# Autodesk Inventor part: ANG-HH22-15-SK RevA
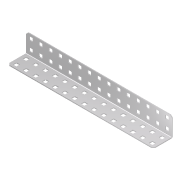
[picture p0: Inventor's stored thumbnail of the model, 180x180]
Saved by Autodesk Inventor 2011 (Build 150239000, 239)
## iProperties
Created: 2007-12
Part Number: ANG-HH22-15-SK RevA
Document SubType Name: Modeling
Density: 1 g/cm^3
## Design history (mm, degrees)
feature "Base1"
workplane "Work Plane1"
workplane "Work Plane2"
sketch "Sketch1" dims "d5" = 25.4
  geometry: L1 (2.286, -23.419)-(188.214, -23.419) reference; L2 (188.214, -23.419)-(190.5, -21.133) reference; L3 (190.5, -21.133)-(190.5, 0) reference; L4 (0, 0)-(190.5, 0) reference; L5 (0, 0)-(0, -21.133) reference; L6 (0, -21.133)-(2.286, -23.419) reference; L7 (186.461, -3.734)-(186.461, -7.341) reference; L8 (185.953, -7.849)-(182.347, -7.849) reference; L9 (181.839, -7.341)-(181.839, -3.734) reference; L10 (182.347, -3.226)-(185.953, -3.226) reference; L11 (173.761, -16.434)-(173.761, -20.041) reference; L12 (173.253, -20.549)-(169.647, -20.549) reference; L13 (169.139, -20.041)-(169.139, -16.434) reference; L14 (169.647, -15.926)-(173.253, -15.926) reference; L15 (173.761, -3.734)-(173.761, -7.341) reference; L16 (173.253, -7.849)-(169.647, -7.849) reference; L17 (169.139, -7.341)-(169.139, -3.734) reference; L18 (169.647, -3.226)-(173.253, -3.226) reference; L19 (161.061, -16.434)-(161.061, -20.041) reference; L20 (160.553, -20.549)-(156.947, -20.549) reference; L21 (156.439, -20.041)-(156.439, -16.434) reference; L22 (156.947, -15.926)-(160.553, -15.926) reference; L23 (161.061, -3.734)-(161.061, -7.341) reference; L24 (160.553, -7.849)-(156.947, -7.849) reference; L25 (156.439, -7.341)-(156.439, -3.734) reference; L26 (156.947, -3.226)-(160.553, -3.226) reference; L27 (148.361, -16.434)-(148.361, -20.041) reference; L28 (147.853, -20.549)-(144.247, -20.549) reference; L29 (143.739, -20.041)-(143.739, -16.434) reference; L30 (144.247, -15.926)-(147.853, -15.926) reference; L31 (148.361, -3.734)-(148.361, -7.341) reference; L32 (147.853, -7.849)-(144.247, -7.849) reference; L33 (143.739, -7.341)-(143.739, -3.734) reference; L34 (144.247, -3.226)-(147.853, -3.226) reference; L35 (135.661, -16.434)-(135.661, -20.041) reference; L36 (135.153, -20.549)-(131.547, -20.549) reference; L37 (131.039, -20.041)-(131.039, -16.434) reference; L38 (131.547, -15.926)-(135.153, -15.926) reference; L39 (135.661, -3.734)-(135.661, -7.341) reference; L40 (135.153, -7.849)-(131.547, -7.849) reference; L41 (131.039, -7.341)-(131.039, -3.734) reference; L42 (131.547, -3.226)-(135.153, -3.226) reference; L43 (122.961, -16.434)-(122.961, -20.041) reference; L44 (122.453, -20.549)-(118.847, -20.549) reference; L45 (118.339, -20.041)-(118.339, -16.434) reference; L46 (118.847, -15.926)-(122.453, -15.926) reference; L47 (122.961, -3.734)-(122.961, -7.341) reference; L48 (122.453, -7.849)-(118.847, -7.849) reference; L49 (118.339, -7.341)-(118.339, -3.734) reference; L50 (118.847, -3.226)-(122.453, -3.226) reference; L51 (110.261, -16.434)-(110.261, -20.041) reference; L52 (109.753, -20.549)-(106.147, -20.549) reference; L53 (105.639, -20.041)-(105.639, -16.434) reference; L54 (106.147, -15.926)-(109.753, -15.926) reference; L55 (110.261, -3.734)-(110.261, -7.341) reference; L56 (109.753, -7.849)-(106.147, -7.849) reference; L57 (105.639, -7.341)-(105.639, -3.734) reference; L58 (106.147, -3.226)-(109.753, -3.226) reference; L59 (97.561, -16.434)-(97.561, -20.041) reference; L60 (97.053, -20.549)-(93.447, -20.549) reference; L61 (92.939, -20.041)-(92.939, -16.434) reference; L62 (93.447, -15.926)-(97.053, -15.926) reference; L63 (97.561, -3.734)-(97.561, -7.341) reference; L64 (97.053, -7.849)-(93.447, -7.849) reference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; C1 r 2.311 at (184.15, -18.237); C2 r 2.311 at (171.45, -18.237); C3 r 2.311 at (158.75, -18.237); C4 r 2.311 at (146.05, -18.237); C5 r 2.311 at (133.35, -18.237); C6 r 2.311 at (120.65, -18.237); C7 r 2.311 at (107.95, -18.237); C8 r 2.311 at (95.25, -18.237); C9 r 2.311 at (82.55, -18.237); C10 r 2.311 at (69.85, -18.237); C11 r 2.311 at (57.15, -18.237); C12 r 2.311 at (44.45, -18.237); C13 r 2.311 at (31.75, -18.237); C14 r 2.311 at (19.05, -18.237); C15 r 2.311 at (6.35, -18.237); A1 r 0.508 centre (185.953, -7.341) between (185.953, -7.849) and (186.461, -7.341) reference; A2 r 0.508 centre (182.347, -7.341) between (181.839, -7.341) and (182.347, -7.849) reference; A3 r 0.508 centre (182.347, -3.734) between (182.347, -3.226) and (181.839, -3.734) reference; A4 r 0.508 centre (185.953, -3.734) between (186.461, -3.734) and (185.953, -3.226) reference; A5 r 0.508 centre (173.253, -20.041) between (173.253, -20.549) and (173.761, -20.041) reference; A6 r 0.508 centre (169.647, -20.041) between (169.139, -20.041) and (169.647, -20.549) reference; A7 r 0.508 centre (169.647, -16.434) between (169.647, -15.926) and (169.139, -16.434) reference; A8 r 0.508 centre (173.253, -16.434) between (173.761, -16.434) and (173.253, -15.926) reference; A9 r 0.508 centre (173.253, -7.341) between (173.253, -7.849) and (173.761, -7.341) reference; A10 r 0.508 centre (169.647, -7.341) between (169.139, -7.341) and (169.647, -7.849) reference; A11 r 0.508 centre (169.647, -3.734) between (169.647, -3.226) and (169.139, -3.734) reference; A12 r 0.508 centre (173.253, -3.734) between (173.761, -3.734) and (173.253, -3.226) reference; A13 r 0.508 centre (160.553, -20.041) between (160.553, -20.549) and (161.061, -20.041) reference; A14 r 0.508 centre (156.947, -20.041) between (156.439, -20.041) and (156.947, -20.549) reference; A15 r 0.508 centre (156.947, -16.434) between (156.947, -15.926) and (156.439, -16.434) reference; A16 r 0.508 centre (160.553, -16.434) between (161.061, -16.434) and (160.553, -15.926) reference; A17 r 0.508 centre (160.553, -7.341) between (160.553, -7.849) and (161.061, -7.341) reference; A18 r 0.508 centre (156.947, -7.341) between (156.439, -7.341) and (156.947, -7.849) reference; A19 r 0.508 centre (156.947, -3.734) between (156.947, -3.226) and (156.439, -3.734) reference; A20 r 0.508 centre (160.553, -3.734) between (161.061, -3.734) and (160.553, -3.226) reference; A21 r 0.508 centre (147.853, -20.041) between (147.853, -20.549) and (148.361, -20.041) reference; A22 r 0.508 centre (144.247, -20.041) between (143.739, -20.041) and (144.247, -20.549) reference; A23 r 0.508 centre (144.247, -16.434) between (144.247, -15.926) and (143.739, -16.434) reference; A24 r 0.508 centre (147.853, -16.434) between (148.361, -16.434) and (147.853, -15.926) reference; A25 r 0.508 centre (147.853, -7.341) between (147.853, -7.849) and (148.361, -7.341) reference; A26 r 0.508 centre (144.247, -7.341) between (143.739, -7.341) and (144.247, -7.849) reference; A27 r 0.508 centre (144.247, -3.734) between (144.247, -3.226) and (143.739, -3.734) reference; A28 r 0.508 centre (147.853, -3.734) between (148.361, -3.734) and (147.853, -3.226) reference; A29 r 0.508 centre (135.153, -20.041) between (135.153, -20.549) and (135.661, -20.041) reference; A30 r 0.508 centre (131.547, -20.041) between (131.039, -20.041) and (131.547, -20.549) reference; A31 r 0.508 centre (131.547, -16.434) between (131.547, -15.926) and (131.039, -16.434) reference; A32 r 0.508 centre (135.153, -16.434) between (135.661, -16.434) and (135.153, -15.926) reference; A33 r 0.508 centre (135.153, -7.341) between (135.153, -7.849) and (135.661, -7.341) reference; A34 r 0.508 centre (131.547, -7.341) between (131.039, -7.341) and (131.547, -7.849) reference; A35 r 0.508 centre (131.547, -3.734) between (131.547, -3.226) and (131.039, -3.734) reference; A36 r 0.508 centre (135.153, -3.734) between (135.661, -3.734) and (135.153, -3.226) reference; A37 r 0.508 centre (122.453, -20.041) between (122.453, -20.549) and (122.961, -20.041) reference; A38 r 0.508 centre (118.847, -20.041) between (118.339, -20.041) and (118.847, -20.549) reference; A39 r 0.508 centre (118.847, -16.434) between (118.847, -15.926) and (118.339, -16.434) reference; A40 r 0.508 centre (122.453, -16.434) between (122.961, -16.434) and (122.453, -15.926) reference; A41 r 0.508 centre (122.453, -7.341) between (122.453, -7.849) and (122.961, -7.341) reference; A42 r 0.508 centre (118.847, -7.341) between (118.339, -7.341) and (118.847, -7.849) reference; A43 r 0.508 centre (118.847, -3.734) between (118.847, -3.226) and (118.339, -3.734) reference; A44 r 0.508 centre (122.453, -3.734) between (122.961, -3.734) and (122.453, -3.226) reference; A45 r 0.508 centre (109.753, -20.041) between (109.753, -20.549) and (110.261, -20.041) reference; A46 r 0.508 centre (106.147, -20.041) between (105.639, -20.041) and (106.147, -20.549) reference; A47 r 0.508 centre (106.147, -16.434) between (106.147, -15.926) and (105.639, -16.434) reference; A48 r 0.508 centre (109.753, -16.434) between (110.261, -16.434) and (109.753, -15.926) reference; A49 r 0.508 centre (109.753, -7.341) between (109.753, -7.849) and (110.261, -7.341) reference; A50 r 0.508 centre (106.147, -7.341) between (105.639, -7.341) and (106.147, -7.849) reference; A51 r 0.508 centre (106.147, -3.734) between (106.147, -3.226) and (105.639, -3.734) reference; A52 r 0.508 centre (109.753, -3.734) between (110.261, -3.734) and (109.753, -3.226) reference; A53 r 0.508 centre (97.053, -20.041) between (97.053, -20.549) and (97.561, -20.041) reference; A54 r 0.508 centre (93.447, -20.041) between (92.939, -20.041) and (93.447, -20.549) reference; A55 r 0.508 centre (93.447, -16.434) between (93.447, -15.926) and (92.939, -16.434) reference; A56 r 0.508 centre (97.053, -16.434) between (97.561, -16.434) and (97.053, -15.926) reference; A57 r 0.508 centre (97.053, -7.341) between (97.053, -7.849) and (97.561, -7.341) reference; A58 r 0.508 centre (93.447, -7.341) between (92.939, -7.341) and (93.447, -7.849) reference; A59 r 0.508 centre (93.447, -3.734) between (93.447, -3.226) and (92.939, -3.734) reference; A60 r 0.508 centre (97.053, -3.734) between (97.561, -3.734) and (97.053, -3.226) reference; A61 r 0.508 centre (84.353, -20.041) between (84.353, -20.549) and (84.861, -20.041) reference; A62 r 0.508 centre (80.747, -20.041) between (80.239, -20.041) and (80.747, -20.549) reference; A63 r 0.508 centre (80.747, -16.434) between (80.747, -15.926) and (80.239, -16.434) reference; A64 r 0.508 centre (84.353, -16.434) between (84.861, -16.434) and (84.353, -15.926) reference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
  constraints: 15 centre point, 3 tangent, 1 horizontal, 28 other
  dimensions: "d2" = 12.7 distance of C1.centre C2.centre
sketch "Sketch2" dims "d12" = 25.4
  geometry: L1 (190.5, 21.133)-(190.5, 0) reference; L2 (190.5, 21.133)-(188.214, 23.419) reference; L3 (2.286, 23.419)-(188.214, 23.419) reference; L4 (2.286, 23.419)-(0, 21.133) reference; L5 (0, 0)-(0, 21.133) reference; L6 (190.5, 0)-(0, 0) reference; L7 (186.461, 7.341)-(186.461, 3.734) reference; L8 (185.953, 3.226)-(182.347, 3.226) reference; L9 (181.839, 3.734)-(181.839, 7.341) reference; L10 (182.347, 7.849)-(185.953, 7.849) reference; L11 (173.761, 20.041)-(173.761, 16.434) reference; L12 (173.253, 15.926)-(169.647, 15.926) reference; L13 (169.139, 16.434)-(169.139, 20.041) reference; L14 (169.647, 20.549)-(173.253, 20.549) reference; L15 (173.761, 7.341)-(173.761, 3.734) reference; L16 (173.253, 3.226)-(169.647, 3.226) reference; L17 (169.139, 3.734)-(169.139, 7.341) reference; L18 (169.647, 7.849)-(173.253, 7.849) reference; L19 (161.061, 20.041)-(161.061, 16.434) reference; L20 (160.553, 15.926)-(156.947, 15.926) reference; L21 (156.439, 16.434)-(156.439, 20.041) reference; L22 (156.947, 20.549)-(160.553, 20.549) reference; L23 (161.061, 7.341)-(161.061, 3.734) reference; L24 (160.553, 3.226)-(156.947, 3.226) reference; L25 (156.439, 3.734)-(156.439, 7.341) reference; L26 (156.947, 7.849)-(160.553, 7.849) reference; L27 (148.361, 20.041)-(148.361, 16.434) reference; L28 (147.853, 15.926)-(144.247, 15.926) reference; L29 (143.739, 16.434)-(143.739, 20.041) reference; L30 (144.247, 20.549)-(147.853, 20.549) reference; L31 (148.361, 7.341)-(148.361, 3.734) reference; L32 (147.853, 3.226)-(144.247, 3.226) reference; L33 (143.739, 3.734)-(143.739, 7.341) reference; L34 (144.247, 7.849)-(147.853, 7.849) reference; L35 (135.661, 20.041)-(135.661, 16.434) reference; L36 (135.153, 15.926)-(131.547, 15.926) reference; L37 (131.039, 16.434)-(131.039, 20.041) reference; L38 (131.547, 20.549)-(135.153, 20.549) reference; L39 (135.661, 7.341)-(135.661, 3.734) reference; L40 (135.153, 3.226)-(131.547, 3.226) reference; L41 (131.039, 3.734)-(131.039, 7.341) reference; L42 (131.547, 7.849)-(135.153, 7.849) reference; L43 (122.961, 20.041)-(122.961, 16.434) reference; L44 (122.453, 15.926)-(118.847, 15.926) reference; L45 (118.339, 16.434)-(118.339, 20.041) reference; L46 (118.847, 20.549)-(122.453, 20.549) reference; L47 (122.961, 7.341)-(122.961, 3.734) reference; L48 (122.453, 3.226)-(118.847, 3.226) reference; L49 (118.339, 3.734)-(118.339, 7.341) reference; L50 (118.847, 7.849)-(122.453, 7.849) reference; L51 (110.261, 20.041)-(110.261, 16.434) reference; L52 (109.753, 15.926)-(106.147, 15.926) reference; L53 (105.639, 16.434)-(105.639, 20.041) reference; L54 (106.147, 20.549)-(109.753, 20.549) reference; L55 (110.261, 7.341)-(110.261, 3.734) reference; L56 (109.753, 3.226)-(106.147, 3.226) reference; L57 (105.639, 3.734)-(105.639, 7.341) reference; L58 (106.147, 7.849)-(109.753, 7.849) reference; L59 (97.561, 20.041)-(97.561, 16.434) reference; L60 (97.053, 15.926)-(93.447, 15.926) reference; L61 (92.939, 16.434)-(92.939, 20.041) reference; L62 (93.447, 20.549)-(97.053, 20.549) reference; L63 (97.561, 7.341)-(97.561, 3.734) reference; L64 (97.053, 3.226)-(93.447, 3.226) reference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; C1 r 2.311 at (184.15, 18.237); C2 r 2.311 at (171.45, 18.237); C3 r 2.311 at (158.75, 18.237); C4 r 2.311 at (146.05, 18.237); C5 r 2.311 at (133.35, 18.237); C6 r 2.311 at (120.65, 18.237); C7 r 2.311 at (107.95, 18.237); C8 r 2.311 at (95.25, 18.237); C9 r 2.311 at (82.55, 18.237); C10 r 2.311 at (69.85, 18.237); C11 r 2.311 at (57.15, 18.237); C12 r 2.311 at (44.45, 18.237); C13 r 2.311 at (31.75, 18.237); C14 r 2.311 at (19.05, 18.237); C15 r 2.311 at (6.35, 18.237); A1 r 0.508 centre (185.953, 3.734) between (185.953, 3.226) and (186.461, 3.734) reference; A2 r 0.508 centre (182.347, 3.734) between (181.839, 3.734) and (182.347, 3.226) reference; A3 r 0.508 centre (182.347, 7.341) between (182.347, 7.849) and (181.839, 7.341) reference; A4 r 0.508 centre (185.953, 7.341) between (186.461, 7.341) and (185.953, 7.849) reference; A5 r 0.508 centre (173.253, 16.434) between (173.253, 15.926) and (173.761, 16.434) reference; A6 r 0.508 centre (169.647, 16.434) between (169.139, 16.434) and (169.647, 15.926) reference; A7 r 0.508 centre (169.647, 20.041) between (169.647, 20.549) and (169.139, 20.041) reference; A8 r 0.508 centre (173.253, 20.041) between (173.761, 20.041) and (173.253, 20.549) reference; A9 r 0.508 centre (173.253, 3.734) between (173.253, 3.226) and (173.761, 3.734) reference; A10 r 0.508 centre (169.647, 3.734) between (169.139, 3.734) and (169.647, 3.226) reference; A11 r 0.508 centre (169.647, 7.341) between (169.647, 7.849) and (169.139, 7.341) reference; A12 r 0.508 centre (173.253, 7.341) between (173.761, 7.341) and (173.253, 7.849) reference; A13 r 0.508 centre (160.553, 16.434) between (160.553, 15.926) and (161.061, 16.434) reference; A14 r 0.508 centre (156.947, 16.434) between (156.439, 16.434) and (156.947, 15.926) reference; A15 r 0.508 centre (156.947, 20.041) between (156.947, 20.549) and (156.439, 20.041) reference; A16 r 0.508 centre (160.553, 20.041) between (161.061, 20.041) and (160.553, 20.549) reference; A17 r 0.508 centre (160.553, 3.734) between (160.553, 3.226) and (161.061, 3.734) reference; A18 r 0.508 centre (156.947, 3.734) between (156.439, 3.734) and (156.947, 3.226) reference; A19 r 0.508 centre (156.947, 7.341) between (156.947, 7.849) and (156.439, 7.341) reference; A20 r 0.508 centre (160.553, 7.341) between (161.061, 7.341) and (160.553, 7.849) reference; A21 r 0.508 centre (147.853, 16.434) between (147.853, 15.926) and (148.361, 16.434) reference; A22 r 0.508 centre (144.247, 16.434) between (143.739, 16.434) and (144.247, 15.926) reference; A23 r 0.508 centre (144.247, 20.041) between (144.247, 20.549) and (143.739, 20.041) reference; A24 r 0.508 centre (147.853, 20.041) between (148.361, 20.041) and (147.853, 20.549) reference; A25 r 0.508 centre (147.853, 3.734) between (147.853, 3.226) and (148.361, 3.734) reference; A26 r 0.508 centre (144.247, 3.734) between (143.739, 3.734) and (144.247, 3.226) reference; A27 r 0.508 centre (144.247, 7.341) between (144.247, 7.849) and (143.739, 7.341) reference; A28 r 0.508 centre (147.853, 7.341) between (148.361, 7.341) and (147.853, 7.849) reference; A29 r 0.508 centre (135.153, 16.434) between (135.153, 15.926) and (135.661, 16.434) reference; A30 r 0.508 centre (131.547, 16.434) between (131.039, 16.434) and (131.547, 15.926) reference; A31 r 0.508 centre (131.547, 20.041) between (131.547, 20.549) and (131.039, 20.041) reference; A32 r 0.508 centre (135.153, 20.041) between (135.661, 20.041) and (135.153, 20.549) reference; A33 r 0.508 centre (135.153, 3.734) between (135.153, 3.226) and (135.661, 3.734) reference; A34 r 0.508 centre (131.547, 3.734) between (131.039, 3.734) and (131.547, 3.226) reference; A35 r 0.508 centre (131.547, 7.341) between (131.547, 7.849) and (131.039, 7.341) reference; A36 r 0.508 centre (135.153, 7.341) between (135.661, 7.341) and (135.153, 7.849) reference; A37 r 0.508 centre (122.453, 16.434) between (122.453, 15.926) and (122.961, 16.434) reference; A38 r 0.508 centre (118.847, 16.434) between (118.339, 16.434) and (118.847, 15.926) reference; A39 r 0.508 centre (118.847, 20.041) between (118.847, 20.549) and (118.339, 20.041) reference; A40 r 0.508 centre (122.453, 20.041) between (122.961, 20.041) and (122.453, 20.549) reference; A41 r 0.508 centre (122.453, 3.734) between (122.453, 3.226) and (122.961, 3.734) reference; A42 r 0.508 centre (118.847, 3.734) between (118.339, 3.734) and (118.847, 3.226) reference; A43 r 0.508 centre (118.847, 7.341) between (118.847, 7.849) and (118.339, 7.341) reference; A44 r 0.508 centre (122.453, 7.341) between (122.961, 7.341) and (122.453, 7.849) reference; A45 r 0.508 centre (109.753, 16.434) between (109.753, 15.926) and (110.261, 16.434) reference; A46 r 0.508 centre (106.147, 16.434) between (105.639, 16.434) and (106.147, 15.926) reference; A47 r 0.508 centre (106.147, 20.041) between (106.147, 20.549) and (105.639, 20.041) reference; A48 r 0.508 centre (109.753, 20.041) between (110.261, 20.041) and (109.753, 20.549) reference; A49 r 0.508 centre (109.753, 3.734) between (109.753, 3.226) and (110.261, 3.734) reference; A50 r 0.508 centre (106.147, 3.734) between (105.639, 3.734) and (106.147, 3.226) reference; A51 r 0.508 centre (106.147, 7.341) between (106.147, 7.849) and (105.639, 7.341) reference; A52 r 0.508 centre (109.753, 7.341) between (110.261, 7.341) and (109.753, 7.849) reference; A53 r 0.508 centre (97.053, 16.434) between (97.053, 15.926) and (97.561, 16.434) reference; A54 r 0.508 centre (93.447, 16.434) between (92.939, 16.434) and (93.447, 15.926) reference; A55 r 0.508 centre (93.447, 20.041) between (93.447, 20.549) and (92.939, 20.041) reference; A56 r 0.508 centre (97.053, 20.041) between (97.561, 20.041) and (97.053, 20.549) reference; A57 r 0.508 centre (97.053, 3.734) between (97.053, 3.226) and (97.561, 3.734) reference; A58 r 0.508 centre (93.447, 3.734) between (92.939, 3.734) and (93.447, 3.226) reference; A59 r 0.508 centre (93.447, 7.341) between (93.447, 7.849) and (92.939, 7.341) reference; A60 r 0.508 centre (97.053, 7.341) between (97.561, 7.341) and (97.053, 7.849) reference; A61 r 0.508 centre (84.353, 16.434) between (84.353, 15.926) and (84.861, 16.434) reference; A62 r 0.508 centre (80.747, 16.434) between (80.239, 16.434) and (80.747, 15.926) reference; A63 r 0.508 centre (80.747, 20.041) between (80.747, 20.549) and (80.239, 20.041) reference; A64 r 0.508 centre (84.353, 20.041) between (84.861, 20.041) and (84.353, 20.549) reference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
  constraints: 15 centre point, 4 tangent, 1 horizontal, 28 other
  dimensions: "d9" = 12.7 distance of C1.centre C2.centre
workplane "Work Plane3"
body "Solid1"
